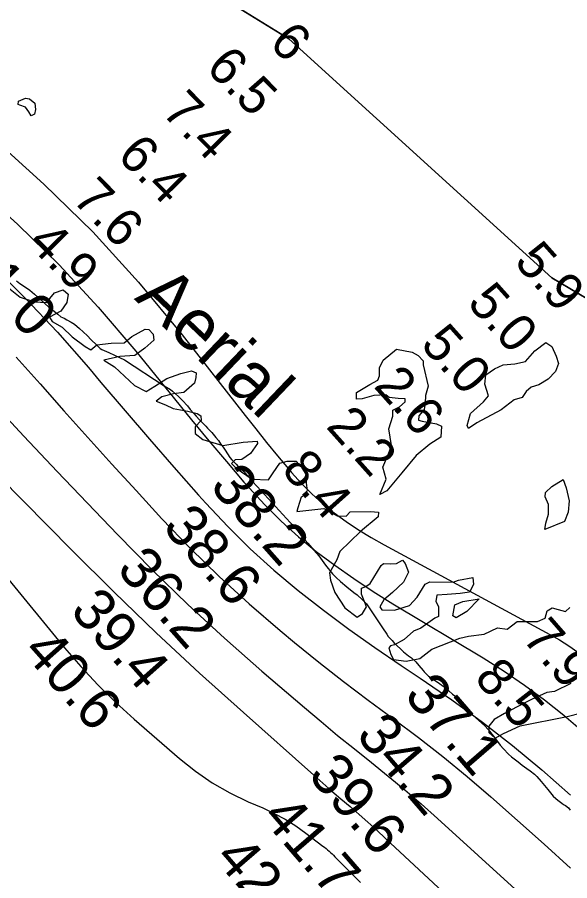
# Model space of a CAD drawing. Extents: x 3245246 to 3283090, y 806824 to 832173.
# Drawn here: x 3268257 to 3269141, y 816212 to 817595 of the extents above; entities that cross this region are included whole.
import ezdxf

# ---------------------------------------------------------------- set-up
doc = ezdxf.new("R2010")
doc.units = 0
for name, color, linetype in [('V-RIVR-EDGE', 7, 'Continuous'), ('V-RIVR-IDEN', 7, 'Continuous'), ('V-RIVR-RANG', 7, 'Continuous'), ('V-ROAD-CNTR', 7, 'Continuous'), ('V-SITE-VEGE', 7, 'Continuous'), ('V-TOPO-DPTH', 7, 'Continuous'), ('V-TOPO-MAJR', 7, 'Continuous'), ('V-TOPO-MINR', 7, 'Continuous'), ('V-TOPO-WATR', 7, 'Continuous')]:
    doc.layers.add(name, color=color, linetype=linetype)

msp = doc.modelspace()

# ---------------------------------------------------------------- linework, layer by layer
at = {"layer": 'V-RIVR-EDGE'}
for points in [[(3268269.8, 817465.6), (3268276.3, 817464.7), (3268285, 817457.7), (3268286.2, 817447.3), (3268284.5, 817439.9), (3268278.8, 817437.3), (3268275.4, 817443.8), (3268270.2, 817451.2), (3268261, 817454.3), (3268258, 817455.2), (3268258.5, 817460.8)], [(3268258.5, 817460.8), (3268269.8, 817465.6)], [(3268232.1, 817170.1), (3268261.2, 817147), (3268284.6, 817139.1), (3268303.3, 817138.2), (3268316.4, 817153.8), (3268330.3, 817158.5), (3268338.1, 817151.6), (3268336.3, 817138.1), (3268326.3, 817124.2), (3268308.5, 817114.7), (3268312.4, 817107.7), (3268328.4, 817098.6), (3268344.5, 817083.3), (3268365.7, 817067.6), (3268374.4, 817062.4), (3268384.4, 817070.6), (3268407, 817073.2), (3268427.9, 817073.5), (3268440.1, 817083.5), (3268461.4, 817095.6), (3268467.5, 817095.2), (3268474.4, 817087.3), (3268475.7, 817077.8), (3268461.3, 817065.2), (3268444.8, 817053.5), (3268420.9, 817051.8), (3268395.2, 817045.8), (3268412.6, 817034.9), (3268444.7, 817005.3), (3268463.3, 816995.6), (3268476.8, 817004.3), (3268496.4, 817016.4), (3268518.6, 817024.6), (3268536, 817028.5), (3268543, 817025.4), (3268542.9, 817018.1), (3268540.8, 817008.9), (3268523.3, 816993.8), (3268507.2, 816992.1), (3268488.5, 816987.3), (3268479.4, 816980.4), (3268494.2, 816974.3), (3268506.3, 816968.6), (3268529.8, 816964.2), (3268545, 816960.2), (3268550.6, 816956.7), (3268551, 816949.4), (3268541.4, 816938.9), (3268541.9, 816928.5), (3268554, 816918.9), (3268585.7, 816909.3), (3268618.3, 816914.4), (3268640.9, 816916.1), (3268641.4, 816912.2), (3268630, 816896.6), (3268616.5, 816886.6), (3268605.6, 816886.2), (3268600, 816880.1), (3268607.4, 816872.7), (3268633, 816855.3), (3268659, 816854.3), (3268666.5, 816865.6), (3268677.4, 816880.8), (3268689.1, 816884.2), (3268703.4, 816883.8), (3268712.1, 816874.6), (3268719.5, 816862), (3268719.4, 816849), (3268721.2, 816837.2), (3268717.2, 816829.8), (3268711.6, 816826.4), (3268705.9, 816809.4), (3268704.6, 816803.4), (3268747.6, 816808), (3268769.3, 816796.7), (3268783.6, 816796.2), (3268789.7, 816803.1), (3268822.3, 816803.5), (3268835, 816802.2), (3268834.9, 816794.8), (3268806.2, 816771.4), (3268773.1, 816739.3), (3268768.7, 816725.8), (3268756.9, 816705.4), (3268758.6, 816693.2), (3268765.5, 816673.7), (3268781.5, 816648.9), (3268801.1, 816634), (3268809.8, 816640.1), (3268815.9, 816650.5), (3268813.3, 816657.9), (3268808.1, 816671), (3268808.1, 816680.5), (3268814.7, 816683.5), (3268822.1, 816688.3), (3268839.5, 816717), (3268843, 816720.4), (3268853.9, 816719.5)], [(3269103, 817074), (3269112.9, 817067.5), (3269119.8, 817052.3), (3269123.3, 817040.5), (3269118.5, 817027.9), (3269106.7, 817015.4), (3269091.9, 817006.3), (3269079.7, 817002.4), (3269071.5, 816995.4), (3269065.4, 816985.9), (3269052.7, 816982.5), (3269031.4, 816966.4), (3268992.7, 816945.7), (3268979.6, 816936.6), (3268977, 816941.3), (3268982.3, 816960.5), (3269003.2, 816979.1), (3269011.5, 816988.6), (3269005.4, 817007.3), (3269007.2, 817022.6), (3269021.1, 817032.1), (3269034.6, 817038.1), (3269053.3, 817039.8), (3269070.7, 817043.7), (3269085.5, 817061)], [(3269085.5, 817061), (3269103, 817074)], [(3268863.9, 817063.3), (3268889.1, 817058.9), (3268899, 817053.3), (3268906.8, 817045), (3268906.8, 817038.5), (3268915, 817004.1), (3268910.6, 816989.3), (3268909.7, 816976.7), (3268908.4, 816966.7), (3268899.7, 816956.8), (3268899.2, 816949.8), (3268904.9, 816948), (3268927.9, 816943.6), (3268936.1, 816940.1), (3268935.2, 816922.3), (3268917.4, 816911.1), (3268895.6, 816892.9), (3268872.5, 816865.5), (3268848.5, 816836.5), (3268837.2, 816830.4), (3268847.3, 816855.2), (3268842.1, 816874.3), (3268851.3, 816896), (3268856.1, 816909), (3268851.8, 816936), (3268858.4, 816956.4), (3268858.4, 816966), (3268868.8, 816971.2), (3268878, 816979), (3268878, 816983.8), (3268866.7, 816984.2), (3268852.4, 816986), (3268847.2, 816990.4), (3268828, 816989.1), (3268808.9, 816983.9), (3268800.2, 816983.5), (3268800.2, 816993.9), (3268821.5, 817006.9), (3268834.2, 817013.9), (3268836.8, 817020.8), (3268836.8, 817033.4), (3268842.9, 817046)], [(3268842.9, 817046), (3268863.9, 817063.3)], [(3269131.1, 816854.9), (3269135.8, 816841.4), (3269140.6, 816820.5), (3269138.8, 816802.3), (3269133.1, 816787.5), (3269101.8, 816774.6), (3269103.1, 816784.5), (3269107.5, 816798.9), (3269107.5, 816814.5), (3269102.3, 816826.7), (3269102.4, 816834.1), (3269112.8, 816843.6)], [(3269112.8, 816843.6), (3269131.1, 816854.9)], [(3268853.9, 816719.5), (3268864.3, 816720.4), (3268873.9, 816725.6), (3268877.8, 816719.9), (3268883.4, 816706), (3268875.5, 816690.4), (3268857.7, 816673.9), (3268843.7, 816662.2), (3268837.6, 816650.5), (3268840.6, 816645.7), (3268860.6, 816645.2), (3268885, 816652.9), (3268897.2, 816666), (3268909.9, 816686.8), (3268917.3, 816690.7), (3268954.6, 816690.2), (3268963.3, 816693.2), (3268986.4, 816697.5), (3268987.2, 816686.6), (3268980.7, 816674.4), (3268965.9, 816671.9), (3268945, 816670.6), (3268928.9, 816669.4), (3268927.2, 816659.4), (3268931.1, 816651.5), (3268931.5, 816635), (3268925.4, 816632.4), (3268903.2, 816616.4), (3268891.4, 816611.6), (3268876.2, 816598.2), (3268860.9, 816590), (3268854.4, 816588.3), (3268851.8, 816584.8), (3268854.8, 816574.3), (3268859.1, 816566.5), (3268879.6, 816563.9), (3268901.3, 816568.1), (3268920.5, 816582.9), (3268965.7, 816600.6), (3268979.6, 816603.6), (3269004.4, 816607), (3269025.8, 816617), (3269041.4, 816615.2)], [(3268996.3, 816663.5), (3268976.7, 816643.2), (3268959.7, 816633.2), (3268954.1, 816636.3), (3268957.2, 816654.1), (3268970.2, 816659.3)], [(3268970.2, 816659.3), (3268996.3, 816663.5)], [(3269041.4, 816615.2), (3269057.1, 816627.3), (3269090.1, 816627.2), (3269102.3, 816632.4), (3269105.4, 816644.1), (3269113.6, 816649.3), (3269123.2, 816646.3), (3269134.5, 816643.2), (3269141.5, 816649.7)], [(3269143.3, 816528), (3269117.2, 816515), (3269104.6, 816513.7), (3269080.2, 816502.5), (3269058.5, 816491.3), (3269037.1, 816480), (3269020.6, 816470), (3269011.9, 816459.6), (3269011.9, 816449.2), (3269021.8, 816440.5), (3269035.3, 816447.8), (3269062.3, 816459.9), (3269137.1, 816475), (3269181, 816486.2)]]:
    msp.add_lwpolyline(points, dxfattribs=at)
at = {"layer": 'V-ROAD-CNTR'}
msp.add_spline([(3265843.1, 823432.9), (3265859, 823417.1), (3265884.4, 823393.5), (3265921.6, 823385.9), (3265988.6, 823351.1), (3266047.2, 823332.3), (3266110.9, 823317.7), (3266174.6, 823302.5), (3266237.9, 823256.1), (3266319, 823213.7), (3266446.2, 823144), (3266598.2, 823070.2), (3266698.3, 823024.2), (3266809.8, 822977.5), (3266902.8, 822954.7), (3266981.5, 822929.4), (3267047, 822922.9), (3267126.7, 822927), (3267196.8, 822934.5), (3267240.8, 822931.2), (3267315.5, 822929), (3267389.5, 822902.9), (3267472.5, 822855.3), (3267548.2, 822799.1), (3267673.2, 822703.2), (3267729.5, 822659.2), (3267800.8, 822580), (3267841.6, 822514.8), (3267890.4, 822443.6), (3267961.5, 822390.3), (3268026.2, 822347.9), (3268097.5, 822313.7), (3268226.8, 822221.5), (3268328.9, 822136.2), (3268438, 822030.2), (3268539.6, 821913.7), (3268611.4, 821855), (3268669.7, 821833), (3268741.6, 821835.2), (3268781, 821862.3), (3268824.2, 821916.6), (3268873.1, 822006.3), (3268932.5, 822098.1), (3268972.1, 822145.5), (3269019.4, 822162), (3269056, 822158.3), (3269086.7, 822138.7), (3269215.7, 821995.6), (3269467.1, 821682.5), (3269665, 821425.3), (3269890.2, 821132.3), (3269935.6, 821060.8), (3269937.8, 820947), (3269911.9, 820878.4), (3269882.4, 820803.4), (3269850.4, 820754.7), (3269820.8, 820702.9), (3269847.5, 820661.4), (3269995.3, 820504.9), (3270135.1, 820342.3), (3270215.8, 820249.2), (3270280.9, 820161.5), (3270409.8, 819983.2), (3270585.2, 819734.7), (3270723.1, 819531.2), (3270847.8, 819342.2), (3270941.2, 819194.9), (3271024.2, 819065), (3271103.7, 818956), (3271217.9, 818809.2), (3271322.1, 818665), (3271450.9, 818481.1), (3271547.8, 818329.9), (3271656.2, 818159), (3271778.9, 817965.4), (3271939, 817707.5), (3272036.6, 817466.5), (3272126.7, 817285.3), (3272211.9, 817051.1), (3272318, 816867.5), (3272429.4, 816683.2), (3272508.6, 816556.2), (3272571.6, 816398.7), (3272670.4, 816197), (3272779.9, 816022.9), (3272872.1, 815803.2), (3272964.7, 815556.6)], degree=3, dxfattribs=at)
at = {"layer": 'V-SITE-VEGE'}
for p, q in [((3268255.5, 817172.8), (3268261.1, 817168.6)), ((3268261.1, 817168.6), (3268270.1, 817162.7)), ((3268270.1, 817162.7), (3268277, 817157.8)), ((3268277, 817157.8), (3268284.3, 817151.8)), ((3268284.3, 817151.8), (3268294.7, 817142.7)), ((3268294.7, 817142.7), (3268307.5, 817130.8)), ((3268307.5, 817130.8), (3268313.4, 817126.2)), ((3268313.4, 817126.2), (3268321.8, 817119.6)), ((3268321.8, 817119.6), (3268326.6, 817115.3)), ((3268326.6, 817115.3), (3268331.8, 817112.9)), ((3268331.8, 817112.9), (3268336.3, 817110.4)), ((3268336.3, 817110.4), (3268343.3, 817106.6)), ((3268343.3, 817106.6), (3268348.5, 817103.4)), ((3268348.5, 817103.4), (3268356.5, 817096.7)), ((3268356.5, 817096.7), (3268362.4, 817091.1)), ((3268362.4, 817091.1), (3268369.3, 817084.8)), ((3268369.3, 817084.8), (3268374.8, 817078.9)), ((3268374.8, 817078.9), (3268384.2, 817069.8)), ((3268384.2, 817069.8), (3268388, 817065.9)), ((3268388, 817065.9), (3268389.7, 817064.5)), ((3268389.7, 817064.5), (3268392.2, 817062.7)), ((3268392.2, 817062.7), (3268403.3, 817058.2)), ((3268403.3, 817058.2), (3268412.7, 817053.6)), ((3268412.7, 817053.6), (3268428.3, 817046.5)), ((3268428.3, 817046.5), (3268492.2, 817004.7)), ((3268492.2, 817004.7), (3268502.3, 816998.8)), ((3268502.3, 816998.8), (3268505.4, 816996.3)), ((3268505.4, 816996.3), (3268514.7, 816987.6)), ((3268514.7, 816987.6), (3268521.3, 816981.3)), ((3268521.3, 816981.3), (3268529.3, 816972.5)), ((3268529.3, 816972.5), (3268533.8, 816966.9)), ((3268533.8, 816966.9), (3268539.7, 816960.3)), ((3268539.7, 816960.3), (3268543.5, 816956.1)), ((3268543.5, 816956.1), (3268548.7, 816950.1)), ((3268548.7, 816950.1), (3268553.2, 816945.2)), ((3268553.2, 816945.2), (3268558.7, 816940)), ((3268558.7, 816940), (3268561.5, 816936.8)), ((3268561.5, 816936.8), (3268565, 816933.3)), ((3268565, 816933.3), (3268568.1, 816929.8)), ((3268568.1, 816929.8), (3268574.6, 816921.8)), ((3268574.6, 816921.8), (3268578.8, 816916.9)), ((3268578.8, 816916.9), (3268582.3, 816912)), ((3268582.3, 816912), (3268586.4, 816906.4)), ((3268586.4, 816906.4), (3268589.5, 816901.5)), ((3268589.5, 816901.5), (3268597.1, 816889.9)), ((3268597.1, 816889.9), (3268600.2, 816886.4)), ((3268600.2, 816886.4), (3268607.2, 816879.1)), ((3268607.2, 816879.1), (3268610.6, 816875.6)), ((3268610.6, 816875.6), (3268615.8, 816870.7)), ((3268615.8, 816870.7), (3268618.9, 816867.9)), ((3268618.9, 816867.9), (3268622.8, 816864)), ((3268622.8, 816864), (3268625.5, 816860.9)), ((3268625.5, 816860.9), (3268632.8, 816852.1)), ((3268632.8, 816852.1), (3268640.8, 816843.3)), ((3268640.8, 816843.3), (3268705.4, 816772.9)), ((3268705.4, 816772.9), (3268713.9, 816760.9)), ((3268713.9, 816760.9), (3268715.8, 816758.7)), ((3268715.8, 816758.7), (3268717.7, 816757.3)), ((3268717.7, 816757.3), (3268722.2, 816752.9)), ((3268722.2, 816752.9), (3268731.8, 816741.7)), ((3268731.8, 816741.7), (3268736, 816736.6)), ((3268736, 816736.6), (3268739.5, 816732.3)), ((3268739.5, 816732.3), (3268750.6, 816717.4)), ((3268750.6, 816717.4), (3268761.7, 816703.6)), ((3268761.7, 816703.6), (3268767.4, 816697.9)), ((3268767.4, 816697.9), (3268774.3, 816691.4)), ((3268774.3, 816691.4), (3268784.5, 816682.8)), ((3268784.5, 816682.8), (3268795.9, 816673.8)), ((3268795.9, 816673.8), (3268801.1, 816669.9)), ((3268801.1, 816669.9), (3268809.5, 816661.9)), ((3268809.5, 816661.9), (3268816, 816655.5)), ((3268816, 816655.5), (3268822.5, 816646)), ((3268822.5, 816646), (3268826.8, 816639.4)), ((3268826.8, 816639.4), (3268841.8, 816617.3)), ((3268841.8, 816617.3), (3268848.8, 816606.7)), ((3268848.8, 816606.7), (3268850.7, 816603.4)), ((3268850.7, 816603.4), (3268857.2, 816596.6)), ((3268857.2, 816596.6), (3268861, 816592.2)), ((3268861, 816592.2), (3268870.1, 816583.9)), ((3268870.1, 816583.9), (3268875.5, 816578.9)), ((3268875.5, 816578.9), (3268883.4, 816572.5)), ((3268883.4, 816572.5), (3268888.3, 816569.2)), ((3268888.3, 816569.2), (3268895.2, 816562.4)), ((3268895.2, 816562.4), (3268899.8, 816557)), ((3268899.8, 816557), (3268907, 816548.6)), ((3268907, 816548.6), (3268908.6, 816546.5)), ((3268908.6, 816546.5), (3268915.4, 816539.6)), ((3268915.4, 816539.6), (3268927.5, 816531.8)), ((3268927.5, 816531.8), (3268941.8, 816521.4)), ((3268941.8, 816521.4), (3268953.6, 816511)), ((3268953.6, 816511), (3268963, 816504.2)), ((3268963, 816504.2), (3268968, 816498.4)), ((3268968, 816498.4), (3268973.4, 816492.6)), ((3268973.4, 816492.6), (3268979.1, 816485)), ((3268979.1, 816485), (3268982.9, 816480.3)), ((3268982.9, 816480.3), (3268990.9, 816472.7)), ((3268990.9, 816472.7), (3269005.3, 816460.2)), ((3269005.3, 816460.2), (3269011.1, 816454.4)), ((3269011.1, 816454.4), (3269019.1, 816443.9)), ((3269019.1, 816443.9), (3269022.6, 816439.5)), ((3269022.6, 816439.5), (3269030.2, 816429.4)), ((3269030.2, 816429.4), (3269035.2, 816423.2)), ((3269035.2, 816423.2), (3269043.2, 816414.9)), ((3269043.2, 816414.9), (3269048.2, 816410.2)), ((3269048.2, 816410.2), (3269058.8, 816402.3)), ((3269058.8, 816402.3), (3269065.2, 816397.3)), ((3269065.2, 816397.3), (3269072.7, 816392)), ((3269072.7, 816392), (3269078, 816388.1)), ((3269078, 816388.1), (3269084.8, 816382.7)), ((3269084.8, 816382.7), (3269089, 816378.7)), ((3269089, 816378.7), (3269095.9, 816371.1)), ((3269095.9, 816371.1), (3269106.6, 816358.1)), ((3269106.6, 816358.1), (3269110.8, 816352.6)), ((3269110.8, 816352.6), (3269115.1, 816347.6)), ((3269115.1, 816347.6), (3269119.2, 816343.6)), ((3269119.2, 816343.6), (3269122.3, 816341.1)), ((3269122.3, 816341.1), (3269128.7, 816336.1)), ((3269128.7, 816336.1), (3269131.3, 816334.3)), ((3269131.3, 816334.3), (3269134.7, 816332.5)), ((3269134.7, 816332.5), (3269139.3, 816328.6)), ((3269139.3, 816328.6), (3269142.3, 816325))]:
    msp.add_line(p, q, dxfattribs=at)
at = {"layer": 'V-TOPO-DPTH'}
for points in [[(3269256.8, 817092.2), (3269113, 817177.8), (3268691.5, 817560.8), (3268545.9, 817650.9)], [(3269256.8, 817092.2), (3269113, 817177.8), (3268691.5, 817560.8), (3268545.9, 817650.9)], [(3268189.1, 817325.2), (3268257.6, 817263.1), (3268323.7, 817198.6), (3268386.2, 817130.6), (3268446.4, 817060.3), (3268508.4, 816983.7), (3268535.9, 816950.1), (3268563.6, 816916.7), (3268591.6, 816883.6), (3268619.8, 816850.6), (3268627.9, 816841.2), (3268653, 816813.9), (3268679.2, 816787.7), (3268706.9, 816763), (3268735.6, 816739.5), (3268765.4, 816717.3), (3268795.7, 816695.9), (3268826.8, 816675.5), (3268858.3, 816655.7), (3269002.8, 816568.8), (3269036.3, 816547.6), (3269069.1, 816525.4), (3269100.9, 816501.8), (3269132, 816477.2), (3269162, 816451.3)]]:
    msp.add_lwpolyline(points, dxfattribs=at)
at = {"layer": 'V-TOPO-MAJR'}
msp.add_lwpolyline([(3268240.7, 816953), (3268267.2, 816924.3), (3268294, 816895.9), (3268320.8, 816867.5), (3268417, 816766.7), (3268472.8, 816709.9), (3268529.8, 816654.3), (3268588.5, 816600.4), (3268648.2, 816547.8), (3268716.7, 816489.3), (3268743.2, 816466.9), (3268769.8, 816444.8), (3268796.8, 816423), (3268823.9, 816401.4), (3268850.9, 816379.7), (3268877.6, 816357.6), (3268903.8, 816334.9), (3268929.6, 816311.9), (3269130.9, 816128.6)], dxfattribs=at)
at = {"layer": 'V-TOPO-MINR'}
for points in [[(3267951.5, 817626), (3268218.2, 817400.8), (3268299.5, 817327.7), (3268377.5, 817251.5), (3268450.7, 817170.6), (3268520.7, 817086.6), (3268621.8, 816957.2), (3268638.8, 816935.6), (3268656, 816914.1), (3268673.5, 816892.8), (3268691.1, 816871.6), (3268696, 816865.8), (3268711.8, 816848.2), (3268728.3, 816831.5), (3268746, 816815.9), (3268764.4, 816801.1), (3268783.7, 816787.4), (3268803.4, 816774.3), (3268823.5, 816762), (3268844.1, 816750.3), (3269109.5, 816606.5), (3269125, 816597.6), (3269140.1, 816588.2), (3269154.6, 816578.1)], [(3268189.1, 817325.2), (3268257.6, 817263.1), (3268323.7, 817198.6), (3268386.2, 817130.6), (3268446.4, 817060.3), (3268508.4, 816983.7), (3268535.9, 816950.1), (3268563.6, 816916.7), (3268591.6, 816883.6), (3268619.8, 816850.6), (3268627.9, 816841.2), (3268653, 816813.9), (3268679.2, 816787.7), (3268706.9, 816763), (3268735.6, 816739.5), (3268765.4, 816717.3), (3268795.7, 816695.9), (3268826.8, 816675.5), (3268858.3, 816655.7), (3269002.8, 816568.8), (3269036.3, 816547.6), (3269069.1, 816525.4), (3269100.9, 816501.8), (3269132, 816477.2), (3269162, 816451.3)], [(3267632.8, 817297.4), (3268049.9, 816929.7), (3268332.5, 816585.2), (3268358.7, 816554.9), (3268385.8, 816525.6), (3268414.4, 816497.6), (3268444, 816470.7), (3268516.7, 816407.7), (3268542.3, 816387.4), (3268569, 816368.9), (3268597.3, 816352.9), (3268626.7, 816338.6), (3268650, 816328.5), (3268668.1, 816319.9), (3268685.8, 816310.4)], [(3268215.8, 817197.8), (3268269.6, 817145.4), (3268321, 817090.6), (3268370.7, 817034.1), (3268390.8, 817010.2), (3268429.4, 816964.7), (3268468.3, 816919.3), (3268507.6, 816874.3), (3268547.2, 816829.6), (3268558.8, 816816.6), (3268593.7, 816779.4), (3268629.7, 816743.5), (3268667.5, 816709.6), (3268706.6, 816676.8), (3268746.9, 816645.6), (3268787.7, 816615.1), (3268829.3, 816585.6), (3268871.5, 816556.9), (3268902.1, 816536.6), (3268952.4, 816502), (3269001.8, 816466.1), (3269049.8, 816428.4), (3269096.8, 816389.5), (3269142.5, 816348.9)], [(3268254.8, 817050.5), (3268293.4, 817007.9), (3268331.4, 816964.8), (3268369.6, 816921.9), (3268408.2, 816879.2), (3268447, 816836.8), (3268488.5, 816791.7), (3268533.6, 816744.8), (3268579.9, 816699.1), (3268628.1, 816655.4), (3268677.5, 816613), (3268700.9, 816593.6), (3268739.7, 816562.2), (3268779, 816531.3), (3268818.8, 816501.1), (3268859, 816471.4), (3268899.1, 816441.5), (3268938.5, 816410.9), (3268977, 816379.1), (3269014.9, 816346.5), (3269100.6, 816270.5), (3269142.8, 816232.2)], [(3268188.7, 816898.5), (3268344, 816741.4), (3268411.2, 816674.8), (3268479.3, 816609.1), (3268548.6, 816544.7), (3268618.8, 816481.2), (3268731.9, 816380.9), (3268746.2, 816368.3), (3268760.6, 816355.7), (3268775.1, 816343.2), (3268789.6, 816330.8), (3268804.1, 816318.3), (3268818.4, 816305.7), (3268832.6, 816292.9), (3268846.7, 816279.9), (3269160.1, 815987.8)], [(3268685.8, 816310.4), (3268702.7, 816299.7), (3268719.1, 816288.1), (3268746.1, 816267.5), (3268748.7, 816265.5), (3268751.2, 816263.5), (3268753.6, 816261.4), (3268756, 816259.3), (3268758.4, 816257.2), (3268760.8, 816255), (3268763.1, 816252.8), (3268765.3, 816250.5), (3268806.4, 816209.1)]]:
    msp.add_lwpolyline(points, dxfattribs=at)
at = {"layer": 'V-TOPO-WATR'}
msp.add_lwpolyline([(3268545.9, 817650.9), (3268691.5, 817560.8), (3269113, 817177.8), (3269256.8, 817092.2)], dxfattribs=at)

# ---------------------------------------------------------------- texts
at = {"layer": 'V-RIVR-IDEN'}
msp.add_text('Aerial ', height=83, rotation=316.3824, dxfattribs=at).set_placement((3268442.9, 817144))
at = {"layer": 'V-RIVR-RANG'}
for s, height, rotation, p in [('6', 60, 314.4298, (3268658.3, 817551.8)), ('6.5', 60, 314.4298, (3268556.9, 817512.4)), ('7.4', 60, 314.4298, (3268486.2, 817441.7)), ('6.4', 60, 314.4298, (3268414.9, 817371.5)), ('7.6', 60, 314.4298, (3268342.9, 817302.2)), ('4.9', 60, 314.4298, (3268271.8, 817231.9)), ('5.9', 60, 311.8101, (3269050.9, 817202.2)), ('41.0', 67, 314.1483, (3268155.9, 817203.1)), ('5.0', 60, 311.8101, (3268975.6, 817136.4)), ('5.0', 60, 311.8101, (3268900.9, 817069.9)), ('2.6', 60, 311.8101, (3268826.1, 817003.6)), ('2.2', 60, 311.8101, (3268749.8, 816938.8)), ('8.4', 60, 311.8101, (3268678.1, 816869)), ('38.2', 67, 311.5383, (3268563.5, 816842.7)), ('38.6', 67, 311.5383, (3268487.6, 816777.5)), ('36.2', 67, 311.5383, (3268414.2, 816709.7)), ('39.4', 67, 311.5383, (3268339.5, 816643.2)), ('7.9', 60, 311.0786, (3269063.7, 816599.6)), ('40.6', 67, 311.5383, (3268263.6, 816578.1)), ('8.5', 60, 311.0786, (3268986.8, 816535.7)), ('37.1', 67, 310.8083, (3268874.6, 816507.7)), ('34.2', 67, 310.8083, (3268797.5, 816444)), ('39.6', 67, 310.8083, (3268720.8, 816379.9)), ('41.7', 67, 310.8083, (3268646.4, 816312.9)), ('42.5', 67, 310.8083, (3268570.9, 816247.4))]:
    msp.add_text(s, height=height, rotation=rotation, dxfattribs=at).set_placement(p)

doc.saveas('drawing.dxf')
